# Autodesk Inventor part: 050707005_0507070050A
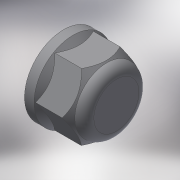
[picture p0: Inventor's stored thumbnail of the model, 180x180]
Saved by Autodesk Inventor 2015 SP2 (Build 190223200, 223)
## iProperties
Created: 2017-05
Part Number: 050707005_0507070050A
Material: Generic
Description: PLASSON CAP 1/2"
Document SubType Name: Modeling
Designer: KIM
Density: 1 g/cm^3
Appearance: Default
Author: KIM
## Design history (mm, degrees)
derived "050707.ipt"
feature "Solid1::050707.ipt"
tag "TaggingFeature1"
body "Solid1"
other parameters: "d0" = 25, "d1" = 1.5, "d2" = 18.631, "d3" = 15, "d4" = 1.5, "d5" = 135 deg, "d6" = 20.4941, "d7" = 37, "d8" = 31.45, "d9" = 30.34, "d10" = 135 deg, "d11" = 4.5, "d13" = 4.5, "d16" = 0, "Rp_" = 18.631, "E_" = 37, "H_" = 25, "l_2" = 15
